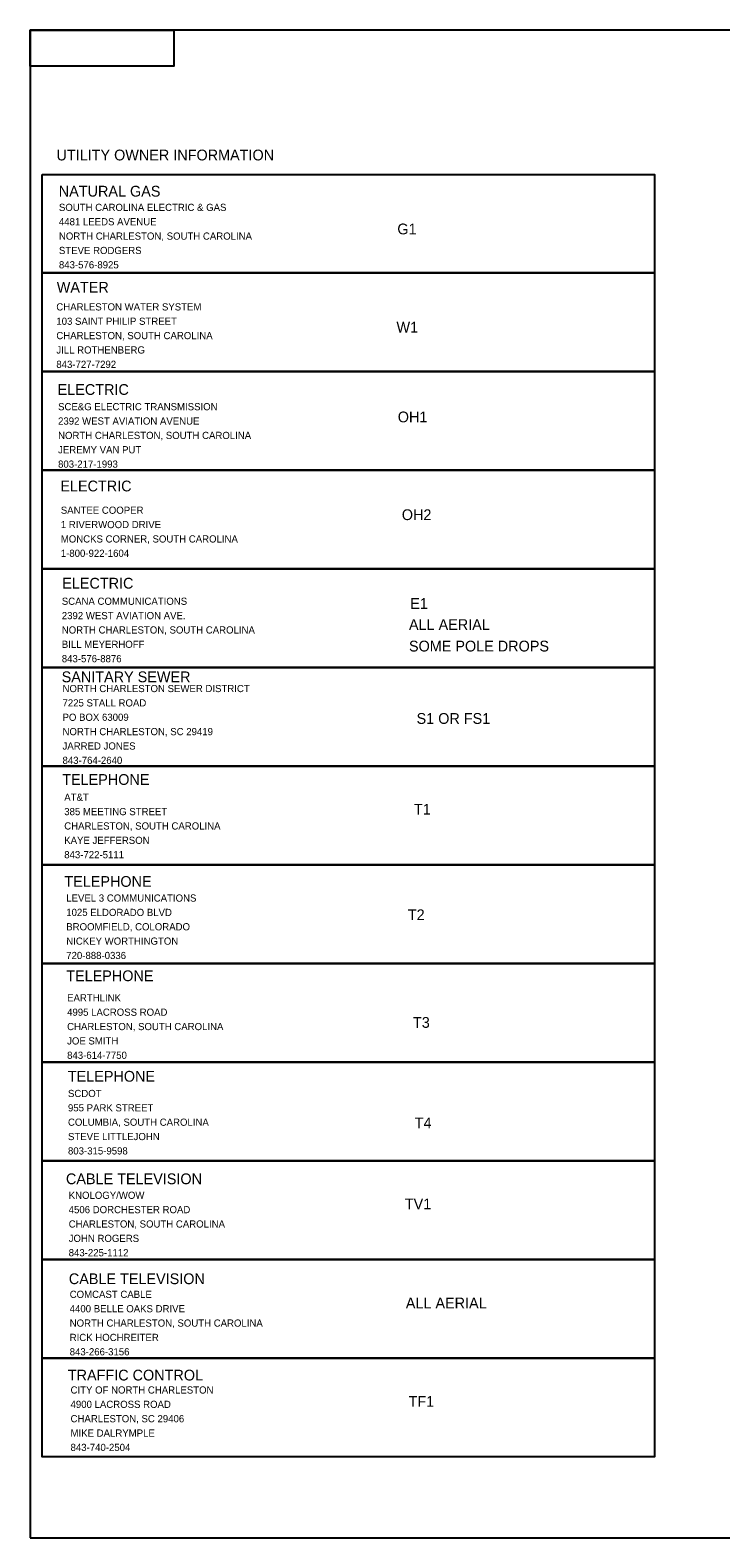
# Model space of a CAD drawing. Extents: x 190073 to 191750, y 195724 to 196797.
# Drawn here: x 190073 to 190554, y 195747 to 196797 of the extents above; entities that cross this region are included whole.
import ezdxf

# ---------------------------------------------------------------- set-up
doc = ezdxf.new("R2010")
doc.units = 0
doc.layers.add('RD_SHT_Bndy', color=7, linetype='Continuous')
doc.layers.add('RD_SHT_TX', color=7, linetype='Continuous')

msp = doc.modelspace()

# ---------------------------------------------------------------- linework, layer by layer
at = {"layer": 'RD_SHT_Bndy'}
for p, q in [((191747.6, 196797.1), (190072.6, 196797.1)), ((190072.6, 196797.1), (190072.6, 195747.1)), ((190072.6, 195897.1), (190072.6, 195747.2)), ((190072.6, 195747.1), (191747.6, 195747.1))]:
    msp.add_line(p, q, dxfattribs=at)
for points in [[(190072.6, 196772.1), (190072.6, 196797.1), (190172.6, 196797.1), (190172.6, 196772.1)], [(190080.9, 196696.7), (190507.4, 196696.7), (190507.4, 196628), (190080.9, 196628)], [(190080.9, 196628), (190507.4, 196628), (190507.4, 196559.3), (190080.9, 196559.3)], [(190080.9, 196559.3), (190507.4, 196559.3), (190507.4, 196490.6), (190080.9, 196490.6)], [(190080.9, 196490.6), (190507.4, 196490.6), (190507.4, 196421.9), (190080.9, 196421.9)], [(190080.9, 196421.9), (190507.4, 196421.9), (190507.4, 196353.2), (190080.9, 196353.2)], [(190080.9, 196353.2), (190507.4, 196353.2), (190507.4, 196284.5), (190080.9, 196284.5)], [(190080.9, 196284.5), (190507.4, 196284.5), (190507.4, 196215.8), (190080.9, 196215.8)], [(190080.9, 196215.8), (190507.4, 196215.8), (190507.4, 196147.1), (190080.9, 196147.1)], [(190080.9, 196147.1), (190507.4, 196147.1), (190507.4, 196078.4), (190080.9, 196078.4)], [(190080.9, 196078.4), (190507.4, 196078.4), (190507.4, 196009.7), (190080.9, 196009.7)], [(190080.9, 196009.7), (190507.4, 196009.7), (190507.4, 195941), (190080.9, 195941)], [(190080.9, 195941), (190507.4, 195941), (190507.4, 195872.3), (190080.9, 195872.3)], [(190080.9, 195872.3), (190507.4, 195872.3), (190507.4, 195803.6), (190080.9, 195803.6)]]:
    msp.add_lwpolyline(points, close=True, dxfattribs=at)

# ---------------------------------------------------------------- texts
at = {"layer": 'RD_SHT_TX'}
for s, height, p in [('UTILITY OWNER INFORMATION', 7.5, (190090.9, 196706.4)), ('NATURAL GAS', 7.5, (190092.5, 196681.2)), ('SOUTH CAROLINA ELECTRIC & GAS', 5, (190092.6, 196671.2)), ('4481 LEEDS AVENUE', 5, (190092.6, 196661.2)), ('NORTH CHARLESTON, SOUTH CAROLINA ', 5, (190092.6, 196651.2)), ('G1', 7.5, (190328.3, 196654.9)), ('STEVE RODGERS', 5, (190092.6, 196641.2)), ('843-576-8925', 5, (190092.6, 196631.2)), ('WATER', 7.5, (190091.1, 196614.3)), ('CHARLESTON WATER SYSTEM', 5, (190090.8, 196601.9)), ('103 SAINT PHILIP STREET', 5, (190090.8, 196591.9)), ('W1', 7.5, (190327.7, 196586.5)), ('CHARLESTON, SOUTH CAROLINA', 5, (190090.8, 196581.9)), ('JILL ROTHENBERG', 5, (190090.8, 196571.9)), ('843-727-7292', 5, (190090.8, 196561.9)), ('ELECTRIC', 7.5, (190091.7, 196543.1)), ('SCE&G ELECTRIC TRANSMISSION', 5, (190092, 196532.4)), ('OH1', 7.5, (190328.6, 196524)), ('2392 WEST AVIATION AVENUE', 5, (190092, 196522.4)), ('NORTH CHARLESTON, SOUTH CAROLINA', 5, (190092, 196512.4)), ('JEREMY VAN PUT', 5, (190092, 196502.4)), ('803-217-1993', 5, (190092, 196492.4)), ('ELECTRIC', 7.5, (190093.6, 196475.9)), ('SANTEE COOPER', 5, (190093.9, 196460.3)), ('1 RIVERWOOD DRIVE', 5, (190093.9, 196450.3)), ('OH2', 7.5, (190331.4, 196455.9)), ('MONCKS CORNER, SOUTH CAROLINA', 5, (190093.9, 196440.3)), ('1-800-922-1604', 5, (190093.9, 196430.3)), ('ELECTRIC', 7.5, (190094.9, 196408.2)), ('SCANA COMMUNICATIONS', 5, (190094.6, 196396.9)), ('2392 WEST AVIATION AVE.', 5, (190094.6, 196386.9)), ('E1', 7.5, (190337.3, 196394.1)), ('NORTH CHARLESTON, SOUTH CAROLINA', 5, (190094.6, 196376.9)), ('ALL AERIAL', 7.5, (190336.4, 196379.4)), ('BILL MEYERHOFF', 5, (190094.6, 196366.9)), ('SOME POLE DROPS', 7.5, (190336.4, 196364.4)), ('843-576-8876', 5, (190094.6, 196356.9)), ('SANITARY SEWER', 7.5, (190094.5, 196343)), ('NORTH CHARLESTON SEWER DISTRICT', 5, (190095.1, 196336.1)), ('7225 STALL ROAD', 5, (190095.1, 196326.1)), ('PO BOX 63009', 5, (190095.1, 196316.1)), ('S1 OR FS1', 7.5, (190341.7, 196314)), ('NORTH CHARLESTON, SC 29419', 5, (190095.1, 196306.1)), ('JARRED JONES', 5, (190095.1, 196296.1)), ('843-764-2640', 5, (190095.1, 196286.1)), ('TELEPHONE', 7.5, (190094.9, 196271.5)), ('AT&T', 5, (190096.3, 196260.4)), ('T1', 7.5, (190339.9, 196250.8)), ('385 MEETING STREET', 5, (190096.3, 196250.4)), ('CHARLESTON, SOUTH CAROLINA ', 5, (190096.3, 196240.4)), ('KAYE JEFFERSON', 5, (190096.3, 196230.4)), ('843-722-5111', 5, (190096.3, 196220.4)), ('TELEPHONE', 7.5, (190096.4, 196200.5)), ('LEVEL 3 COMMUNICATIONS', 5, (190097.7, 196190.2)), ('1025 ELDORADO BLVD', 5, (190097.7, 196180.2)), ('T2', 7.5, (190335.6, 196177.3)), ('BROOMFIELD, COLORADO', 5, (190097.7, 196170.2)), ('NICKEY WORTHINGTON', 5, (190097.7, 196160.2)), ('720-888-0336', 5, (190097.7, 196150.2)), ('TELEPHONE', 7.5, (190097.7, 196134.8)), ('EARTHLINK', 5, (190098.3, 196120.7)), ('4995 LACROSS ROAD', 5, (190098.3, 196110.7)), ('T3', 7.5, (190339.2, 196102.3)), ('CHARLESTON, SOUTH CAROLINA', 5, (190098.3, 196100.7)), ('JOE SMITH', 5, (190098.3, 196090.7)), ('843-614-7750', 5, (190098.3, 196080.7)), ('TELEPHONE', 7.5, (190098.8, 196064.8)), ('SCDOT', 5, (190098.9, 196054.1)), ('955 PARK STREET', 5, (190098.9, 196044.1)), ('COLUMBIA, SOUTH CAROLINA', 5, (190098.9, 196034.1)), ('T4', 7.5, (190340.4, 196032.3)), ('STEVE LITTLEJOHN', 5, (190098.9, 196024.1)), ('803-315-9598', 5, (190098.9, 196014.1)), ('CABLE TELEVISION', 7.5, (190097.5, 195993.4)), ('KNOLOGY/WOW', 5, (190099.4, 195983.2)), ('TV1', 7.5, (190333.5, 195975.9)), ('4506 DORCHESTER ROAD', 5, (190099.4, 195973.2)), ('CHARLESTON, SOUTH CAROLINA', 5, (190099.4, 195963.2)), ('JOHN ROGERS', 5, (190099.4, 195953.2)), ('843-225-1112', 5, (190099.4, 195943.2)), ('CABLE TELEVISION', 7.5, (190099.5, 195923.8)), ('4400 BELLE OAKS DRIVE', 5, (190100.1, 195904.2)), ('COMCAST CABLE', 5, (190100.1, 195914.2)), ('ALL AERIAL', 7.5, (190334.2, 195906.9)), ('NORTH CHARLESTON, SOUTH CAROLINA', 5, (190100.1, 195894.2)), ('RICK HOCHREITER', 5, (190100.1, 195884.2)), ('843-266-3156', 5, (190100.1, 195874.2)), ('TRAFFIC CONTROL', 7.5, (190098.8, 195856.7)), ('CITY OF NORTH CHARLESTON', 5, (190100.7, 195847.6)), ('4900 LACROSS ROAD', 5, (190100.7, 195837.6)), ('TF1', 7.5, (190336.1, 195838.4)), ('CHARLESTON, SC 29406', 5, (190100.7, 195827.6)), ('MIKE DALRYMPLE', 5, (190100.7, 195817.6)), ('843-740-2504', 5, (190100.7, 195807.6))]:
    msp.add_text(s, height=height, dxfattribs=at).set_placement(p)

doc.saveas('drawing.dxf')
